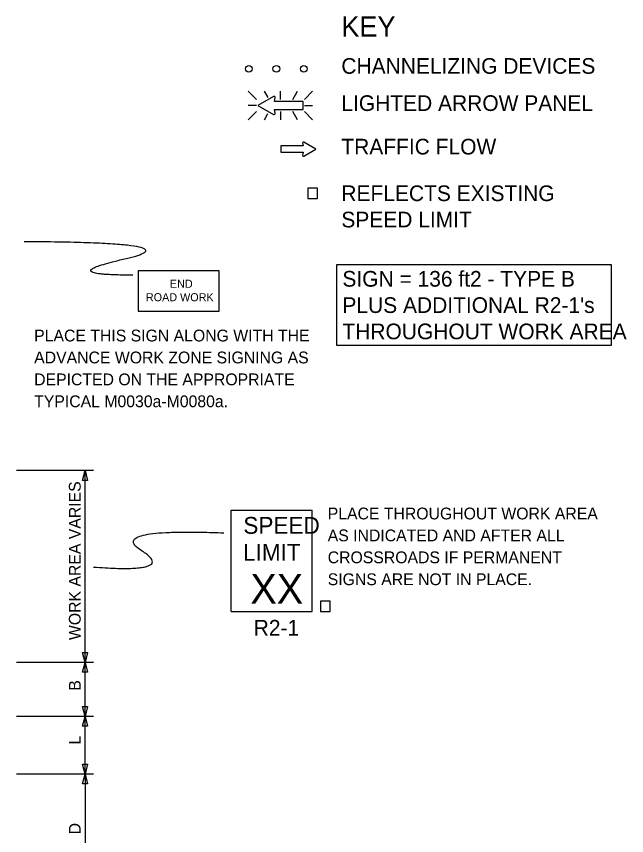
# Model space of a CAD drawing. Extents: x 16739 to 18475, y 7218 to 8197.
# Drawn here: x 17058.5 to 17420.3, y 7711 to 8196.9 of the extents above; entities that cross this region are included whole.
import ezdxf

# ---------------------------------------------------------------- set-up
doc = ezdxf.new("R2010")
doc.units = 0
for name, color, linetype in [('MT_SCRATCH_LEVEL_E', 7, 'Continuous'), ('TRAFFIC_SIGNS_PR', 7, 'Continuous'), ('TYPICAL_TEXT_DIMEN_EX', 7, 'Continuous'), ('TYPICAL_TEXT_DIMEN_PR', 7, 'Continuous')]:
    doc.layers.add(name, color=color, linetype=linetype)

msp = doc.modelspace()

# ---------------------------------------------------------------- linework, layer by layer
at = {"layer": 'MT_SCRATCH_LEVEL_E'}
for p, q in [((17228.52, 8120.03), (17215.27, 8120.03)), ((17215.27, 8120.03), (17215.27, 8116.29)), ((17228.21, 8121.81), (17228.52, 8120.03)), ((17236.13, 8118.18), (17228.89, 8122.29)), ((17215.27, 8116.29), (17228.52, 8116.29)), ((17228.52, 8116.29), (17228.21, 8114.51)), ((17228.89, 8114.03), (17236.13, 8118.18))]:
    msp.add_line(p, q, dxfattribs=at)
for centre, start, end in [((17228.67, 8121.88), 60.4248, 189.9638), ((17228.67, 8114.44), 170.0362, 299.7731)]:
    msp.add_arc(centre, 0.463, start, end, dxfattribs=at)
at = {"layer": 'TRAFFIC_SIGNS_PR'}
for p, q in [((17195.99, 8152.59), (17200.92, 8147.66)), ((17207.75, 8148.77), (17205.55, 8152.59)), ((17215.07, 8147.66), (17215.07, 8152.59)), ((17222.31, 8147.66), (17225.16, 8152.59)), ((17229.22, 8147.66), (17234.16, 8152.59)), ((17200.92, 8144.1), (17195.99, 8144.1)), ((17229.22, 8144.1), (17234.16, 8144.1)), ((17195.99, 8135.61), (17200.92, 8140.55)), ((17205.5, 8135.61), (17207.62, 8139.27)), ((17215.07, 8140.55), (17215.07, 8135.61)), ((17225.2, 8135.61), (17222.35, 8140.55)), ((17229.22, 8140.55), (17234.16, 8135.61)), ((17185.84, 7903.95), (17233.84, 7903.95)), ((17185.84, 7843.95), (17185.84, 7903.95)), ((17233.84, 7843.95), (17233.84, 7903.95)), ((17185.84, 7843.95), (17233.84, 7843.95))]:
    msp.add_line(p, q, dxfattribs=at)
for points in [[(17211, 8149.38), (17201.71, 8144.1), (17211, 8138.78)], [(17211.88, 8139.41), (17211.48, 8141.68), (17228.49, 8141.68), (17228.49, 8146.48), (17211.48, 8146.48), (17211.88, 8148.76)]]:
    msp.add_lwpolyline(points, dxfattribs=at)
for points in [[(17231.35, 8088.82), (17236.94, 8088.82), (17236.94, 8094.99), (17231.35, 8094.99)], [(17130.74, 8022.01), (17178.74, 8022.01), (17178.74, 8046.01), (17130.74, 8046.01)], [(17238.86, 7843.95), (17244.45, 7843.95), (17244.45, 7850.12), (17238.86, 7850.12)]]:
    msp.add_lwpolyline(points, close=True, dxfattribs=at)
for centre in [(17196.33, 8165.79), (17212.63, 8165.79), (17228.93, 8165.79)]:
    msp.add_circle(centre, 2, dxfattribs=at)
for centre, radius, start, end in [((17211.29, 8148.85), 0.598, 350.7308, 118.8916), ((17211.29, 8139.31), 0.597, 241.4833, 9.9593)]:
    msp.add_arc(centre, radius, start, end, dxfattribs=at)
for points in [[(17127.44, 8043.42), (17080.21, 8043.42), (17165.23, 8062.77), (17063.15, 8063.26)], [(17104.2, 7870.3), (17153.98, 7866.55), (17111.61, 7893.4), (17181.49, 7890.58)]]:
    msp.add_open_spline(points, degree=2, dxfattribs=at)
at = {"layer": 'TYPICAL_TEXT_DIMEN_EX'}
msp.add_lwpolyline([(17248.45, 8049.71), (17411.21, 8049.71), (17411.21, 8001.64), (17248.45, 8001.64)], close=True, dxfattribs=at)
at = {"layer": 'TYPICAL_TEXT_DIMEN_PR'}
for p, q in [((17104.15, 7927.5), (17058.45, 7927.5)), ((17097.58, 7921.64), (17099.15, 7927.5)), ((17099.15, 7813.78), (17099.15, 7927.5)), ((17099.15, 7927.5), (17100.72, 7921.64)), ((17099.15, 7921.64), (17097.58, 7921.64)), ((17100.72, 7921.64), (17099.15, 7921.64)), ((17099.15, 7813.78), (17097.58, 7819.64)), ((17097.58, 7819.64), (17099.15, 7819.64)), ((17099.15, 7819.64), (17100.72, 7819.64)), ((17100.72, 7819.64), (17099.15, 7813.78)), ((17104.15, 7813.78), (17058.45, 7813.78)), ((17097.58, 7807.92), (17099.15, 7813.78)), ((17099.15, 7781.72), (17099.15, 7813.78)), ((17099.15, 7813.78), (17100.72, 7807.92)), ((17099.15, 7807.92), (17097.58, 7807.92)), ((17100.72, 7807.92), (17099.15, 7807.92)), ((17099.15, 7781.72), (17097.58, 7787.58)), ((17097.58, 7787.58), (17099.15, 7787.58)), ((17099.15, 7787.58), (17100.72, 7787.58)), ((17100.72, 7787.58), (17099.15, 7781.72)), ((17104.15, 7781.72), (17058.45, 7781.72)), ((17097.58, 7775.86), (17099.15, 7781.72)), ((17099.15, 7747.53), (17099.15, 7781.72)), ((17099.15, 7781.72), (17100.72, 7775.86)), ((17099.15, 7775.86), (17097.58, 7775.86)), ((17100.72, 7775.86), (17099.15, 7775.86)), ((17099.15, 7747.53), (17097.58, 7753.39)), ((17097.58, 7753.39), (17099.15, 7753.39)), ((17099.15, 7753.39), (17100.72, 7753.39)), ((17100.72, 7753.39), (17099.15, 7747.53)), ((17104.15, 7747.53), (17058.45, 7747.53)), ((17097.58, 7741.67), (17099.15, 7747.53)), ((17099.15, 7747.53), (17099.15, 7677.53)), ((17099.15, 7747.53), (17100.72, 7741.67)), ((17099.15, 7741.67), (17097.58, 7741.67)), ((17100.72, 7741.67), (17099.15, 7741.67))]:
    msp.add_line(p, q, dxfattribs=at)

# ---------------------------------------------------------------- texts
at = {"layer": 'TRAFFIC_SIGNS_PR'}
for s, height, p in [('END', 4.789, (17149.49, 8035.92)), ('ROAD WORK', 4.789, (17135.25, 8027.94)), ('PLACE THIS SIGN ALONG WITH THE', 7, (17069, 8004.1)), ('ADVANCE WORK ZONE SIGNING AS', 7, (17069, 7991.1)), ('DEPICTED ON THE APPROPRIATE', 7, (17069, 7978.1)), ('TYPICAL M0030a-M0080a.', 7, (17069, 7965.1)), ('PLACE THROUGHOUT WORK AREA', 7, (17243.09, 7898.56)), ('SPEED', 10, (17193.05, 7890.02)), ('AS INDICATED AND AFTER ALL', 7, (17243.09, 7885.56)), ('LIMIT', 10, (17192.85, 7874.02)), ('CROSSROADS IF PERMANENT', 7, (17243.09, 7872.56)), ('SIGNS ARE NOT IN PLACE.', 7, (17243.09, 7859.56)), ('XX', 17.538, (17197.23, 7848.64)), ('R2-1', 9.3, (17199.19, 7829.65))]:
    msp.add_text(s, height=height, dxfattribs=at).set_placement(p)
at = {"layer": 'TYPICAL_TEXT_DIMEN_EX'}
for s, height, p in [('KEY', 12, (17251.17, 8184.9)), ('CHANNELIZING DEVICES', 9.3, (17251.17, 8162.85)), ('LIGHTED ARROW PANEL', 9.3, (17251.17, 8140.8)), ('TRAFFIC FLOW', 9.3, (17251.17, 8114.99)), ('REFLECTS EXISTING', 9.3, (17251.17, 8087.34)), ('SPEED LIMIT', 9.3, (17251.17, 8071.74)), ('SIGN = 136 ft2 - TYPE B', 9.3, (17251.79, 8036.6)), ("PLUS ADDITIONAL R2-1's", 9.3, (17251.79, 8021)), ('THROUGHOUT WORK AREA', 9.3, (17251.79, 8005.4))]:
    msp.add_text(s, height=height, dxfattribs=at).set_placement(p)
at = {"layer": 'TYPICAL_TEXT_DIMEN_PR'}
for s, p in [('WORK AREA VARIES', (17096.59, 7827)), ('B', (17096.59, 7796.98)), ('L', (17096.59, 7765.01)), ('D', (17096.59, 7711.75))]:
    msp.add_text(s, height=7, rotation=90, dxfattribs=at).set_placement(p)

doc.saveas('drawing.dxf')
